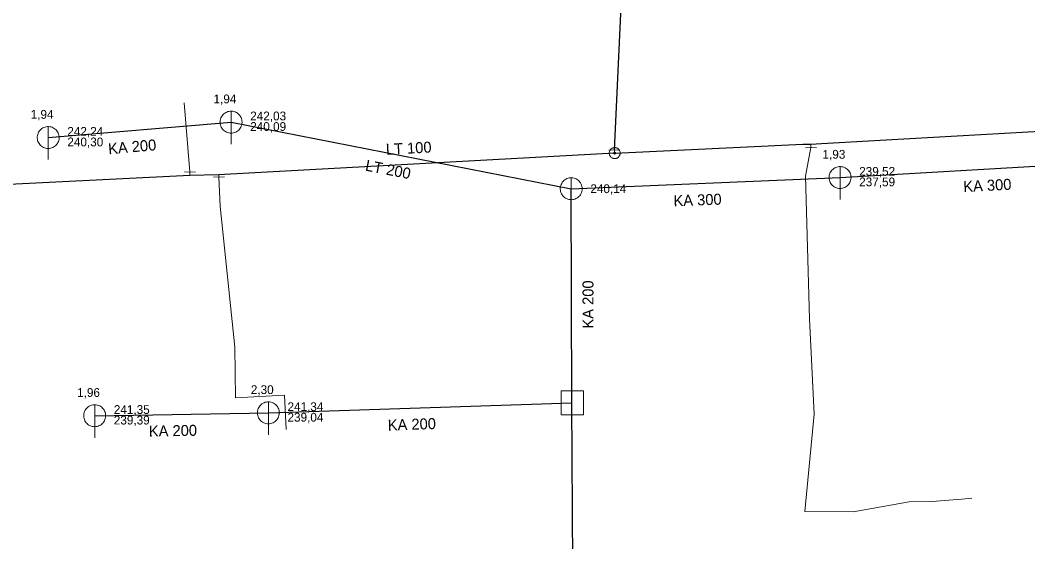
# Model space of a CAD drawing. Extents: x -777996 to -777727, y -976581 to -976199.
# Drawn here: x -777889.9 to -777798.1, y -976426.1 to -976378.6 of the extents above; entities that cross this region are included whole.
import ezdxf

# ---------------------------------------------------------------- set-up
doc = ezdxf.new("R2010")
doc.units = 0
doc.header["$LTSCALE"] = 0.32
doc.linetypes.add('MEDIUM_DASHED', pattern=[4.5, 3, -1.5])
for name, color, linetype, lineweight in [('1', 7, 'MEDIUM_DASHED', 25), ('13', 7, 'Continuous', 13), ('14', 7, 'Continuous', 25), ('17', 7, 'Continuous', 25), ('22', 7, 'Continuous', 13), ('34', 7, 'Continuous', 13), ('47', 7, 'Continuous', 13)]:
    doc.layers.add(name, color=color, linetype=linetype, lineweight=lineweight)

msp = doc.modelspace()

# ---------------------------------------------------------------- linework, layer by layer
at = {"layer": '13'}
msp.add_line((-777874.451, -976392.41), (-777874.991, -976386.129), dxfattribs=at)
for points in [[(-777817.87, -976390.19), (-777818.381, -976392.806), (-777818, -976405.794), (-777817.568, -976414.473), (-777818.414, -976423.344), (-777814.017, -976423.364), (-777808.919, -976422.452), (-777806.859, -976422.432), (-777804.129, -976422.195), (-777803.221, -976422.116)], [(-777871.803, -976392.87), (-777871.684, -976395.535), (-777870.366, -976408.353), (-777870.284, -976412.984), (-777865.84, -976412.745), (-777865.688, -976415.855)]]:
    msp.add_lwpolyline(points, dxfattribs=at)
at = {"layer": '14'}
for p, q in [((-777887.362, -976389.278), (-777870.702, -976387.873)), ((-777870.702, -976387.873), (-777839.71, -976393.936)), ((-777839.71, -976393.936), (-777815.219, -976392.916)), ((-777839.649, -976413.423), (-777839.71, -976393.936)), ((-777867.305, -976414.346), (-777839.649, -976413.423)), ((-777839.462, -976452.855), (-777839.649, -976413.423)), ((-777883.129, -976414.607), (-777867.305, -976414.346))]:
    msp.add_line(p, q, dxfattribs=at)
at = {"layer": '14', "lineweight": 13}
for p, q in [((-777817.883, -976389.866), (-777817.87, -976390.19)), ((-777835.751, -976390.694), (-777835.78, -976390.413)), ((-777874.445, -976392.723), (-777874.451, -976392.41)), ((-777871.809, -976392.66), (-777871.803, -976392.87))]:
    msp.add_line(p, q, dxfattribs=at)
at = {"layer": '14'}
msp.add_lwpolyline([(-777815.219, -976392.916), (-777786.952, -976391.269), (-777779.87, -976390.911)], dxfattribs=at)
at = {"layer": '17'}
for points in [[(-777835.78, -976390.413), (-777831.355, -976295.405), (-777831.422, -976293.534)], [(-777835.751, -976390.694), (-777818.616, -976389.892), (-777817.883, -976389.866), (-777816.903, -976389.831), (-777811.028, -976389.493), (-777795.936, -976388.625), (-777794.949, -976388.572), (-777781.49, -976387.851)], [(-777835.751, -976390.694), (-777871.295, -976392.649), (-777871.809, -976392.66), (-777874.445, -976392.723), (-777907.426, -976394.361)]]:
    msp.add_lwpolyline(points, dxfattribs=at)
at = {"layer": '22'}
for p, q in [((-777870.702, -976389.873), (-777870.701, -976386.873)), ((-777887.362, -976391.278), (-777887.361, -976388.278)), ((-777815.219, -976394.917), (-777815.218, -976391.917)), ((-777839.71, -976395.936), (-777839.709, -976392.936)), ((-777883.13, -976416.608), (-777883.129, -976413.608)), ((-777867.305, -976416.347), (-777867.304, -976413.347))]:
    msp.add_line(p, q, dxfattribs=at)
for points in [[(-777869.702, -976387.873), (-777869.707, -976387.764), (-777869.725, -976387.656), (-777869.755, -976387.55), (-777869.795, -976387.449), (-777869.847, -976387.352), (-777869.909, -976387.262), (-777869.981, -976387.179), (-777870.061, -976387.105), (-777870.149, -976387.039), (-777870.243, -976386.984), (-777870.343, -976386.939), (-777870.448, -976386.906), (-777870.555, -976386.884), (-777870.664, -976386.874), (-777870.774, -976386.876), (-777870.882, -976386.89), (-777870.989, -976386.915), (-777871.092, -976386.952), (-777871.19, -976387.001), (-777871.282, -976387.059), (-777871.368, -976387.128), (-777871.445, -976387.205), (-777871.514, -976387.291), (-777871.573, -976387.383), (-777871.621, -976387.481), (-777871.658, -976387.584), (-777871.684, -976387.691), (-777871.698, -976387.799), (-777871.701, -976387.909), (-777871.691, -976388.018), (-777871.67, -976388.125), (-777871.636, -976388.229), (-777871.592, -976388.329), (-777871.537, -976388.424), (-777871.471, -976388.512), (-777871.397, -976388.592), (-777871.314, -976388.664), (-777871.224, -976388.726), (-777871.128, -976388.778), (-777871.026, -976388.819), (-777870.921, -976388.849), (-777870.813, -976388.867), (-777870.703, -976388.873), (-777870.594, -976388.867), (-777870.486, -976388.849), (-777870.381, -976388.82), (-777870.279, -976388.779), (-777870.182, -976388.727), (-777870.092, -976388.665), (-777870.009, -976388.594), (-777869.934, -976388.514), (-777869.869, -976388.426), (-777869.813, -976388.332), (-777869.769, -976388.232), (-777869.735, -976388.128), (-777869.713, -976388.02), (-777869.703, -976387.911)], [(-777886.362, -976389.278), (-777886.367, -976389.169), (-777886.385, -976389.061), (-777886.415, -976388.955), (-777886.455, -976388.854), (-777886.507, -976388.757), (-777886.569, -976388.667), (-777886.641, -976388.584), (-777886.721, -976388.51), (-777886.809, -976388.444), (-777886.903, -976388.389), (-777887.003, -976388.344), (-777887.108, -976388.311), (-777887.215, -976388.289), (-777887.324, -976388.279), (-777887.434, -976388.281), (-777887.542, -976388.295), (-777887.649, -976388.32), (-777887.752, -976388.357), (-777887.85, -976388.406), (-777887.942, -976388.464), (-777888.028, -976388.533), (-777888.105, -976388.61), (-777888.174, -976388.696), (-777888.233, -976388.788), (-777888.281, -976388.886), (-777888.318, -976388.989), (-777888.344, -976389.096), (-777888.358, -976389.204), (-777888.361, -976389.314), (-777888.351, -976389.423), (-777888.33, -976389.53), (-777888.296, -976389.634), (-777888.252, -976389.734), (-777888.197, -976389.829), (-777888.131, -976389.917), (-777888.057, -976389.997), (-777887.974, -976390.069), (-777887.884, -976390.131), (-777887.788, -976390.183), (-777887.686, -976390.224), (-777887.581, -976390.254), (-777887.473, -976390.272), (-777887.363, -976390.278), (-777887.254, -976390.272), (-777887.146, -976390.254), (-777887.041, -976390.225), (-777886.939, -976390.184), (-777886.842, -976390.132), (-777886.752, -976390.07), (-777886.669, -976389.999), (-777886.594, -976389.919), (-777886.529, -976389.831), (-777886.473, -976389.737), (-777886.429, -976389.637), (-777886.395, -976389.533), (-777886.373, -976389.425), (-777886.363, -976389.316)], [(-777814.219, -976392.917), (-777814.224, -976392.808), (-777814.242, -976392.7), (-777814.272, -976392.594), (-777814.312, -976392.493), (-777814.364, -976392.396), (-777814.426, -976392.306), (-777814.498, -976392.223), (-777814.578, -976392.149), (-777814.666, -976392.083), (-777814.76, -976392.028), (-777814.86, -976391.983), (-777814.965, -976391.95), (-777815.072, -976391.928), (-777815.181, -976391.918), (-777815.291, -976391.92), (-777815.399, -976391.934), (-777815.506, -976391.959), (-777815.609, -976391.996), (-777815.707, -976392.045), (-777815.799, -976392.103), (-777815.885, -976392.172), (-777815.962, -976392.249), (-777816.031, -976392.335), (-777816.09, -976392.427), (-777816.138, -976392.525), (-777816.175, -976392.628), (-777816.201, -976392.735), (-777816.215, -976392.843), (-777816.218, -976392.953), (-777816.208, -976393.062), (-777816.187, -976393.169), (-777816.153, -976393.273), (-777816.109, -976393.373), (-777816.054, -976393.468), (-777815.988, -976393.556), (-777815.914, -976393.636), (-777815.831, -976393.708), (-777815.741, -976393.77), (-777815.645, -976393.822), (-777815.543, -976393.863), (-777815.438, -976393.893), (-777815.33, -976393.911), (-777815.22, -976393.917), (-777815.111, -976393.911), (-777815.003, -976393.893), (-777814.898, -976393.864), (-777814.796, -976393.823), (-777814.699, -976393.771), (-777814.609, -976393.709), (-777814.526, -976393.638), (-777814.451, -976393.558), (-777814.386, -976393.47), (-777814.33, -976393.376), (-777814.286, -976393.276), (-777814.252, -976393.172), (-777814.23, -976393.064), (-777814.22, -976392.955)], [(-777838.71, -976393.936), (-777838.715, -976393.827), (-777838.733, -976393.719), (-777838.763, -976393.613), (-777838.803, -976393.512), (-777838.855, -976393.415), (-777838.917, -976393.325), (-777838.989, -976393.242), (-777839.069, -976393.168), (-777839.157, -976393.102), (-777839.251, -976393.047), (-777839.351, -976393.002), (-777839.456, -976392.969), (-777839.563, -976392.947), (-777839.672, -976392.937), (-777839.782, -976392.939), (-777839.89, -976392.953), (-777839.997, -976392.978), (-777840.1, -976393.015), (-777840.198, -976393.064), (-777840.29, -976393.122), (-777840.376, -976393.191), (-777840.453, -976393.268), (-777840.522, -976393.354), (-777840.581, -976393.446), (-777840.629, -976393.544), (-777840.666, -976393.647), (-777840.692, -976393.754), (-777840.706, -976393.862), (-777840.709, -976393.972), (-777840.699, -976394.081), (-777840.678, -976394.188), (-777840.644, -976394.292), (-777840.6, -976394.392), (-777840.545, -976394.487), (-777840.479, -976394.575), (-777840.405, -976394.655), (-777840.322, -976394.727), (-777840.232, -976394.789), (-777840.136, -976394.841), (-777840.034, -976394.882), (-777839.929, -976394.912), (-777839.821, -976394.93), (-777839.711, -976394.936), (-777839.602, -976394.93), (-777839.494, -976394.912), (-777839.389, -976394.883), (-777839.287, -976394.842), (-777839.19, -976394.79), (-777839.1, -976394.728), (-777839.017, -976394.657), (-777838.942, -976394.577), (-777838.877, -976394.489), (-777838.821, -976394.395), (-777838.777, -976394.295), (-777838.743, -976394.191), (-777838.721, -976394.083), (-777838.711, -976393.974)], [(-777840.63, -976412.334), (-777838.597, -976412.334), (-777838.597, -976414.527), (-777840.63, -976414.527)], [(-777882.13, -976414.608), (-777882.135, -976414.499), (-777882.153, -976414.391), (-777882.183, -976414.285), (-777882.223, -976414.184), (-777882.275, -976414.087), (-777882.337, -976413.997), (-777882.409, -976413.914), (-777882.489, -976413.84), (-777882.577, -976413.774), (-777882.671, -976413.719), (-777882.771, -976413.674), (-777882.876, -976413.641), (-777882.983, -976413.619), (-777883.092, -976413.609), (-777883.202, -976413.611), (-777883.31, -976413.625), (-777883.417, -976413.65), (-777883.52, -976413.687), (-777883.618, -976413.736), (-777883.71, -976413.794), (-777883.796, -976413.863), (-777883.873, -976413.94), (-777883.942, -976414.026), (-777884.001, -976414.118), (-777884.049, -976414.216), (-777884.086, -976414.319), (-777884.112, -976414.426), (-777884.126, -976414.534), (-777884.129, -976414.644), (-777884.119, -976414.753), (-777884.098, -976414.86), (-777884.064, -976414.964), (-777884.02, -976415.064), (-777883.965, -976415.159), (-777883.899, -976415.247), (-777883.825, -976415.327), (-777883.742, -976415.399), (-777883.652, -976415.461), (-777883.556, -976415.513), (-777883.454, -976415.554), (-777883.349, -976415.584), (-777883.241, -976415.602), (-777883.131, -976415.608), (-777883.022, -976415.602), (-777882.914, -976415.584), (-777882.809, -976415.555), (-777882.707, -976415.514), (-777882.61, -976415.462), (-777882.52, -976415.4), (-777882.437, -976415.329), (-777882.362, -976415.249), (-777882.297, -976415.161), (-777882.241, -976415.067), (-777882.197, -976414.967), (-777882.163, -976414.863), (-777882.141, -976414.755), (-777882.131, -976414.646)], [(-777866.305, -976414.347), (-777866.31, -976414.238), (-777866.328, -976414.13), (-777866.358, -976414.024), (-777866.398, -976413.923), (-777866.45, -976413.826), (-777866.512, -976413.736), (-777866.584, -976413.653), (-777866.664, -976413.579), (-777866.752, -976413.513), (-777866.846, -976413.458), (-777866.946, -976413.413), (-777867.051, -976413.38), (-777867.158, -976413.358), (-777867.267, -976413.348), (-777867.377, -976413.35), (-777867.485, -976413.364), (-777867.592, -976413.389), (-777867.695, -976413.426), (-777867.793, -976413.475), (-777867.885, -976413.533), (-777867.971, -976413.602), (-777868.048, -976413.679), (-777868.117, -976413.765), (-777868.176, -976413.857), (-777868.224, -976413.955), (-777868.261, -976414.058), (-777868.287, -976414.165), (-777868.301, -976414.273), (-777868.304, -976414.383), (-777868.294, -976414.492), (-777868.273, -976414.599), (-777868.239, -976414.703), (-777868.195, -976414.803), (-777868.14, -976414.898), (-777868.074, -976414.986), (-777868, -976415.066), (-777867.917, -976415.138), (-777867.827, -976415.2), (-777867.731, -976415.252), (-777867.629, -976415.293), (-777867.524, -976415.323), (-777867.416, -976415.341), (-777867.306, -976415.347), (-777867.197, -976415.341), (-777867.089, -976415.323), (-777866.984, -976415.294), (-777866.882, -976415.253), (-777866.785, -976415.201), (-777866.695, -976415.139), (-777866.612, -976415.068), (-777866.537, -976414.988), (-777866.472, -976414.9), (-777866.416, -976414.806), (-777866.372, -976414.706), (-777866.338, -976414.602), (-777866.316, -976414.494), (-777866.306, -976414.385)]]:
    msp.add_lwpolyline(points, close=True, dxfattribs=at)
at = {"layer": '34'}
for p, q in [((-777835.28, -976390.408), (-777836.279, -976390.416)), ((-777817.37, -976390.171), (-777818.369, -976390.207)), ((-777874.95, -976392.399), (-777873.951, -976392.421)), ((-777871.303, -976392.847), (-777872.302, -976392.891))]:
    msp.add_line(p, q, dxfattribs=at)
at = {"layer": '47'}
for points in [[(-777835.251, -976390.671), (-777835.256, -976390.619), (-777835.267, -976390.567), (-777835.283, -976390.518), (-777835.303, -976390.47), (-777835.329, -976390.424), (-777835.36, -976390.381), (-777835.395, -976390.343), (-777835.434, -976390.308), (-777835.475, -976390.276), (-777835.521, -976390.25), (-777835.569, -976390.228), (-777835.618, -976390.212), (-777835.669, -976390.2), (-777835.721, -976390.195), (-777835.773, -976390.194), (-777835.825, -976390.199), (-777835.877, -976390.21), (-777835.927, -976390.226), (-777835.974, -976390.246), (-777836.02, -976390.272), (-777836.063, -976390.303), (-777836.102, -976390.338), (-777836.137, -976390.377), (-777836.169, -976390.418), (-777836.194, -976390.464), (-777836.216, -976390.512), (-777836.233, -976390.561), (-777836.244, -976390.612), (-777836.249, -976390.664), (-777836.25, -976390.716), (-777836.245, -976390.768), (-777836.234, -976390.82), (-777836.219, -976390.87), (-777836.198, -976390.917), (-777836.172, -976390.963), (-777836.142, -976391.006), (-777836.107, -976391.045), (-777836.068, -976391.08), (-777836.026, -976391.112), (-777835.98, -976391.137), (-777835.932, -976391.159), (-777835.884, -976391.176), (-777835.832, -976391.187), (-777835.78, -976391.192), (-777835.728, -976391.193), (-777835.676, -976391.188), (-777835.624, -976391.177), (-777835.575, -976391.162), (-777835.527, -976391.141), (-777835.481, -976391.115), (-777835.438, -976391.085), (-777835.4, -976391.05), (-777835.365, -976391.011), (-777835.333, -976390.969), (-777835.307, -976390.923), (-777835.285, -976390.875), (-777835.269, -976390.827), (-777835.257, -976390.775), (-777835.252, -976390.723)], [(-777835.669, -976390.69), (-777835.669, -976390.681), (-777835.671, -976390.673), (-777835.674, -976390.665), (-777835.677, -976390.657), (-777835.681, -976390.649), (-777835.687, -976390.643), (-777835.692, -976390.636), (-777835.698, -976390.63), (-777835.706, -976390.625), (-777835.713, -976390.621), (-777835.721, -976390.617), (-777835.729, -976390.614), (-777835.737, -976390.613), (-777835.745, -976390.611), (-777835.754, -976390.612), (-777835.763, -976390.612), (-777835.771, -976390.614), (-777835.779, -976390.617), (-777835.787, -976390.62), (-777835.795, -976390.624), (-777835.801, -976390.63), (-777835.808, -976390.635), (-777835.814, -976390.641), (-777835.82, -976390.649), (-777835.823, -976390.656), (-777835.827, -976390.664), (-777835.83, -976390.672), (-777835.831, -976390.68), (-777835.833, -976390.688), (-777835.832, -976390.697), (-777835.832, -976390.706), (-777835.83, -976390.714), (-777835.827, -976390.722), (-777835.824, -976390.73), (-777835.82, -976390.738), (-777835.815, -976390.745), (-777835.809, -976390.751), (-777835.803, -976390.757), (-777835.795, -976390.763), (-777835.788, -976390.766), (-777835.78, -976390.77), (-777835.772, -976390.773), (-777835.764, -976390.774), (-777835.756, -976390.776), (-777835.747, -976390.775), (-777835.738, -976390.775), (-777835.73, -976390.773), (-777835.722, -976390.77), (-777835.714, -976390.767), (-777835.706, -976390.763), (-777835.699, -976390.758), (-777835.693, -976390.752), (-777835.687, -976390.746), (-777835.682, -976390.738), (-777835.678, -976390.731), (-777835.674, -976390.723), (-777835.671, -976390.715), (-777835.67, -976390.707), (-777835.668, -976390.699)]]:
    msp.add_lwpolyline(points, close=True, dxfattribs=at)

# ---------------------------------------------------------------- texts
at = {"layer": '1'}
for s, p in [('1,94', (-777872.301, -976386.161)), ('1,94', (-777888.961, -976387.566)), ('1,93', (-777816.819, -976391.205)), ('240,14', (-777837.967, -976394.335)), ('1,96', (-777884.729, -976412.896)), ('2,30', (-777868.904, -976412.635))]:
    msp.add_text(s, height=0.8, dxfattribs=at).set_placement(p)
for s, rotation, p in [('KA 200', 5, (-777881.854, -976390.805)), ('LT 100', 3, (-777856.572, -976390.851)), ('LT 200', 349, (-777858.531, -976392.276)), ('KA 300', 3, (-777803.964, -976394.248)), ('KA 300', 2, (-777830.378, -976395.534)), ('KA 200', 90, (-777837.684, -976406.673)), ('KA 200', 2, (-777856.408, -976415.968)), ('KA 200', 1, (-777878.184, -976416.511))]:
    msp.add_text(s, height=1, rotation=rotation, dxfattribs=at).set_placement(p)
at = {"layer": '22'}
for s, p in [('242,03', (-777868.959, -976387.712)), ('240,09', (-777868.959, -976388.672)), ('242,24', (-777885.619, -976389.117)), ('240,30', (-777885.619, -976390.077)), ('239,52', (-777813.476, -976392.757)), ('237,59', (-777813.476, -976393.717)), ('241,35', (-777881.387, -976414.448)), ('241,34', (-777865.562, -976414.187)), ('239,39', (-777881.387, -976415.408)), ('239,04', (-777865.562, -976415.147))]:
    msp.add_text(s, height=0.8, dxfattribs=at).set_placement(p)

doc.saveas('drawing.dxf')
